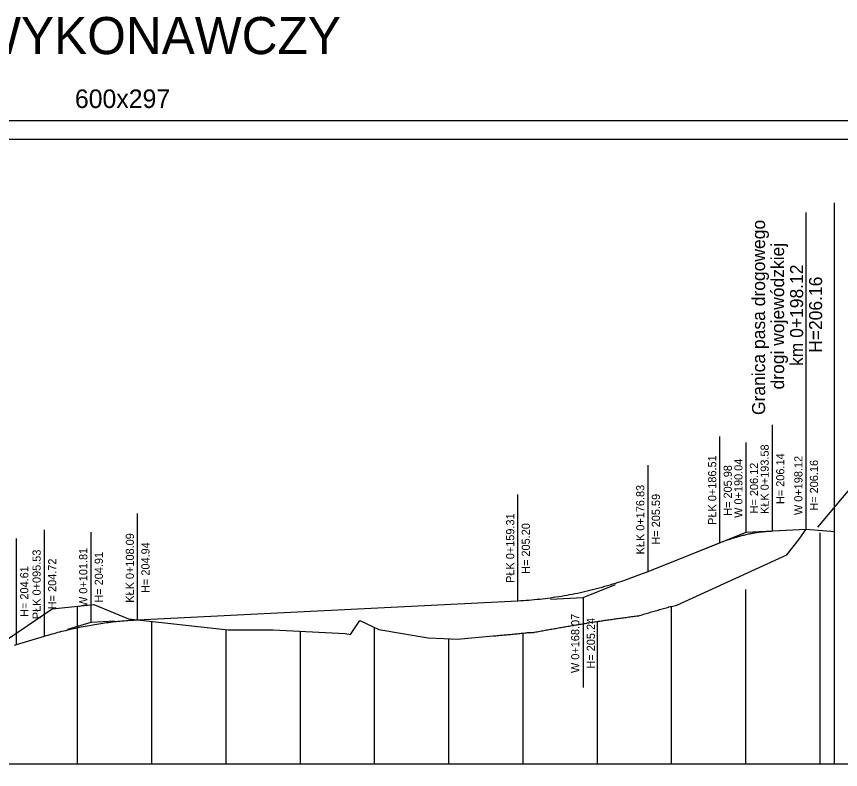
# Model space of a CAD drawing. Extents: x 6513080 to 6513380, y 6022307 to 6022469.
# Drawn here: x 6513209.5 to 6513320.4, y 6022367.8 to 6022469.3 of the extents above; entities that cross this region are included whole.
import ezdxf

# ---------------------------------------------------------------- set-up
doc = ezdxf.new("R2010")
doc.units = 0
for name, color, linetype in [('1', 7, 'Continuous'), ('42', 7, 'Continuous'), ('CONSTRUCTION_CLASS', 7, 'Continuous'), ('maxp_opisy', 7, 'Continuous'), ('maxp_ramka_2', 7, 'Continuous')]:
    doc.layers.add(name, color=color, linetype=linetype)

msp = doc.modelspace()

# ---------------------------------------------------------------- linework, layer by layer
for p, q in [((6513294.53, 6022394.49), (6513307.74, 6022399.78)), ((6513307.74, 6022399.78), (6513315.82, 6022400.17)), ((6513311.28, 6022399.95), (6513315.82, 6022400.17)), ((6513294.53, 6022394.49), (6513304.21, 6022398.37)), ((6513225.79, 6022387.98), (6513277.01, 6022390.55)), ((6513225.79, 6022387.98), (6513277.01, 6022390.55)), ((6513209.47, 6022384.65), (6513213.23, 6022385.78)), ((6513209.47, 6022384.65), (6513213.23, 6022385.78))]:
    msp.add_line(p, q)
for points in [[(6513304.21, 6022398.37), (6513304.36, 6022398.43), (6513304.51, 6022398.49), (6513304.65, 6022398.54), (6513304.8, 6022398.6), (6513304.95, 6022398.65), (6513305.1, 6022398.7), (6513305.24, 6022398.76), (6513305.39, 6022398.81), (6513305.54, 6022398.86), (6513305.68, 6022398.91), (6513305.83, 6022398.95), (6513305.98, 6022399), (6513306.13, 6022399.04), (6513306.27, 6022399.09), (6513306.42, 6022399.13), (6513306.57, 6022399.17), (6513306.71, 6022399.22), (6513306.86, 6022399.26), (6513307.01, 6022399.29), (6513307.16, 6022399.33), (6513307.3, 6022399.37), (6513307.45, 6022399.4), (6513307.6, 6022399.44), (6513307.89, 6022399.51), (6513308.04, 6022399.54), (6513308.19, 6022399.57), (6513308.33, 6022399.6), (6513308.48, 6022399.62), (6513308.63, 6022399.65), (6513308.78, 6022399.68), (6513308.92, 6022399.7), (6513309.07, 6022399.73), (6513309.22, 6022399.75), (6513309.36, 6022399.77), (6513309.51, 6022399.79), (6513309.66, 6022399.81), (6513309.81, 6022399.83), (6513309.95, 6022399.84), (6513310.1, 6022399.86), (6513310.25, 6022399.88), (6513310.39, 6022399.89), (6513310.54, 6022399.9), (6513310.69, 6022399.91), (6513310.84, 6022399.93), (6513310.98, 6022399.94), (6513311.13, 6022399.94), (6513311.28, 6022399.95)], [(6513277.01, 6022390.55), (6513277.38, 6022390.57), (6513277.74, 6022390.59), (6513278.11, 6022390.61), (6513278.47, 6022390.64), (6513278.84, 6022390.67), (6513279.2, 6022390.7), (6513279.57, 6022390.74), (6513279.93, 6022390.78), (6513280.3, 6022390.82), (6513280.66, 6022390.86), (6513281.03, 6022390.91), (6513281.39, 6022390.96), (6513281.76, 6022391.01), (6513282.12, 6022391.06), (6513282.49, 6022391.12), (6513282.85, 6022391.18), (6513283.22, 6022391.24), (6513283.58, 6022391.31), (6513283.95, 6022391.37), (6513284.31, 6022391.44), (6513284.68, 6022391.52), (6513285.04, 6022391.59), (6513285.41, 6022391.67), (6513286.14, 6022391.84), (6513286.5, 6022391.92), (6513286.87, 6022392.01), (6513287.23, 6022392.1), (6513287.6, 6022392.2), (6513287.96, 6022392.29), (6513288.33, 6022392.39), (6513288.69, 6022392.5), (6513289.06, 6022392.6), (6513289.42, 6022392.71), (6513289.79, 6022392.82), (6513290.15, 6022392.93), (6513290.52, 6022393.05), (6513290.88, 6022393.16), (6513291.25, 6022393.29), (6513291.61, 6022393.41), (6513291.98, 6022393.54), (6513292.34, 6022393.66), (6513292.71, 6022393.8), (6513293.07, 6022393.93), (6513293.44, 6022394.07), (6513293.8, 6022394.21), (6513294.17, 6022394.35), (6513294.53, 6022394.49)], [(6513277.01, 6022390.55), (6513277.38, 6022390.57), (6513277.74, 6022390.59), (6513278.11, 6022390.61), (6513278.47, 6022390.64), (6513278.84, 6022390.67), (6513279.2, 6022390.7), (6513279.57, 6022390.74), (6513279.93, 6022390.78), (6513280.3, 6022390.82), (6513280.66, 6022390.86), (6513281.03, 6022390.91), (6513281.39, 6022390.96), (6513281.76, 6022391.01), (6513282.12, 6022391.06), (6513282.49, 6022391.12), (6513282.85, 6022391.18), (6513283.22, 6022391.24), (6513283.58, 6022391.31), (6513283.95, 6022391.37), (6513284.31, 6022391.44), (6513284.68, 6022391.52), (6513285.04, 6022391.59), (6513285.41, 6022391.67), (6513286.14, 6022391.84), (6513286.5, 6022391.92), (6513286.87, 6022392.01), (6513287.23, 6022392.1), (6513287.6, 6022392.2), (6513287.96, 6022392.29), (6513288.33, 6022392.39), (6513288.69, 6022392.5), (6513289.06, 6022392.6), (6513289.42, 6022392.71), (6513289.79, 6022392.82), (6513290.15, 6022392.93), (6513290.52, 6022393.05), (6513290.88, 6022393.16), (6513291.25, 6022393.29), (6513291.61, 6022393.41), (6513291.98, 6022393.54), (6513292.34, 6022393.66), (6513292.71, 6022393.8), (6513293.07, 6022393.93), (6513293.44, 6022394.07), (6513293.8, 6022394.21), (6513294.17, 6022394.35), (6513294.53, 6022394.49)], [(6513213.23, 6022385.78), (6513213.49, 6022385.86), (6513213.75, 6022385.93), (6513214.01, 6022386.01), (6513214.27, 6022386.08), (6513214.54, 6022386.15), (6513214.8, 6022386.23), (6513215.06, 6022386.3), (6513215.32, 6022386.36), (6513215.58, 6022386.43), (6513215.84, 6022386.5), (6513216.11, 6022386.56), (6513216.37, 6022386.62), (6513216.63, 6022386.69), (6513216.89, 6022386.75), (6513217.15, 6022386.81), (6513217.41, 6022386.86), (6513217.68, 6022386.92), (6513217.94, 6022386.97), (6513218.2, 6022387.03), (6513218.46, 6022387.08), (6513218.72, 6022387.13), (6513218.98, 6022387.18), (6513219.25, 6022387.23), (6513219.77, 6022387.32), (6513220.03, 6022387.36), (6513220.29, 6022387.41), (6513220.55, 6022387.45), (6513220.82, 6022387.49), (6513221.08, 6022387.53), (6513221.34, 6022387.56), (6513221.6, 6022387.6), (6513221.86, 6022387.63), (6513222.12, 6022387.67), (6513222.39, 6022387.7), (6513222.65, 6022387.73), (6513222.91, 6022387.76), (6513223.17, 6022387.78), (6513223.43, 6022387.81), (6513223.69, 6022387.83), (6513223.96, 6022387.86), (6513224.22, 6022387.88), (6513224.48, 6022387.9), (6513224.74, 6022387.92), (6513225, 6022387.94), (6513225.26, 6022387.95), (6513225.53, 6022387.97), (6513225.79, 6022387.98)], [(6513213.23, 6022385.78), (6513213.49, 6022385.86), (6513213.75, 6022385.93), (6513214.01, 6022386.01), (6513214.27, 6022386.08), (6513214.54, 6022386.15), (6513214.8, 6022386.23), (6513215.06, 6022386.3), (6513215.32, 6022386.36), (6513215.58, 6022386.43), (6513215.84, 6022386.5), (6513216.11, 6022386.56), (6513216.37, 6022386.62), (6513216.63, 6022386.69), (6513216.89, 6022386.75), (6513217.15, 6022386.81), (6513217.41, 6022386.86), (6513217.68, 6022386.92), (6513217.94, 6022386.97), (6513218.2, 6022387.03), (6513218.46, 6022387.08), (6513218.72, 6022387.13), (6513218.98, 6022387.18), (6513219.25, 6022387.23), (6513219.77, 6022387.32), (6513220.03, 6022387.36), (6513220.29, 6022387.41), (6513220.55, 6022387.45), (6513220.82, 6022387.49), (6513221.08, 6022387.53), (6513221.34, 6022387.56), (6513221.6, 6022387.6), (6513221.86, 6022387.63), (6513222.12, 6022387.67), (6513222.39, 6022387.7), (6513222.65, 6022387.73), (6513222.91, 6022387.76), (6513223.17, 6022387.78), (6513223.43, 6022387.81), (6513223.69, 6022387.83), (6513223.96, 6022387.86), (6513224.22, 6022387.88), (6513224.48, 6022387.9), (6513224.74, 6022387.92), (6513225, 6022387.94), (6513225.26, 6022387.95), (6513225.53, 6022387.97), (6513225.79, 6022387.98)], [(6513209.21, 6022384.57), (6513209.47, 6022384.65)], [(6513209.21, 6022384.57), (6513209.47, 6022384.65)]]:
    msp.add_lwpolyline(points)
at = {"layer": '1'}
for p, q in [((6513305.98, 6022399.08), (6513307.74, 6022399.78)), ((6513307.74, 6022399.78), (6513309.51, 6022399.87)), ((6513315.82, 6022400.17), (6513319.69, 6022399.86)), ((6513317.7, 6022368.56), (6513317.7, 6022399.68)), ((6513285.77, 6022390.98), (6513290.15, 6022392.74)), ((6513307.7, 6022368.56), (6513307.7, 6022392.05)), ((6513281.39, 6022390.77), (6513285.77, 6022390.98)), ((6513217.7, 6022368.56), (6513217.7, 6022389.82)), ((6513297.7, 6022368.56), (6513297.7, 6022389.79)), ((6513216.37, 6022386.72), (6513219.51, 6022387.67)), ((6513219.51, 6022387.67), (6513222.65, 6022387.83)), ((6513227.7, 6022368.56), (6513227.7, 6022387.76)), ((6513287.7, 6022368.56), (6513287.7, 6022387.76)), ((6513237.7, 6022368.56), (6513237.7, 6022386.66)), ((6513247.7, 6022368.56), (6513247.7, 6022386.46)), ((6513257.7, 6022368.56), (6513257.7, 6022386.96)), ((6513277.7, 6022368.56), (6513277.7, 6022386.19)), ((6513267.7, 6022368.56), (6513267.7, 6022385.43)), ((6513217.7, 6022368.56), (6513217.7, 6022370.56)), ((6513227.7, 6022368.56), (6513227.7, 6022369.56)), ((6513237.7, 6022368.56), (6513237.7, 6022369.56)), ((6513247.7, 6022368.56), (6513247.7, 6022369.56)), ((6513257.7, 6022368.56), (6513257.7, 6022369.56)), ((6513267.7, 6022368.56), (6513267.7, 6022369.56)), ((6513277.7, 6022368.56), (6513277.7, 6022369.56)), ((6513287.7, 6022368.56), (6513287.7, 6022369.56)), ((6513297.7, 6022368.56), (6513297.7, 6022369.56)), ((6513307.7, 6022368.56), (6513307.7, 6022369.56)), ((6513317.7, 6022368.56), (6513317.7, 6022370.56)), ((6513117.7, 6022368.56), (6513327.7, 6022368.56))]:
    msp.add_line(p, q, dxfattribs=at)
msp.add_lwpolyline([(6513207.39, 6022384.79), (6513214.28, 6022389.47), (6513219.87, 6022390.04), (6513224.57, 6022388.1), (6513237.96, 6022386.63), (6513244.04, 6022386.65), (6513253.74, 6022386.15), (6513254.46, 6022386.02), (6513255.73, 6022387.88), (6513258.29, 6022386.69), (6513264.93, 6022385.53), (6513267.02, 6022385.47), (6513268.82, 6022385.37), (6513273.67, 6022385.81), (6513273.85, 6022385.82), (6513274.03, 6022385.84), (6513274.21, 6022385.85), (6513274.39, 6022385.87), (6513274.57, 6022385.89), (6513274.75, 6022385.9), (6513274.93, 6022385.92), (6513275.11, 6022385.94), (6513275.29, 6022385.95), (6513275.46, 6022385.97), (6513275.64, 6022385.99), (6513275.82, 6022386), (6513276, 6022386.02), (6513276.18, 6022386.04), (6513276.36, 6022386.06), (6513276.54, 6022386.07), (6513276.72, 6022386.09), (6513276.9, 6022386.11), (6513277.08, 6022386.13), (6513277.26, 6022386.14), (6513277.44, 6022386.16), (6513277.61, 6022386.18), (6513277.79, 6022386.2), (6513277.97, 6022386.22), (6513278.15, 6022386.23), (6513278.28, 6022386.25), (6513278.33, 6022386.25), (6513278.51, 6022386.26), (6513278.69, 6022386.27), (6513278.87, 6022386.28), (6513279.05, 6022386.29), (6513279.14, 6022386.29), (6513279.23, 6022386.31), (6513279.41, 6022386.34), (6513279.59, 6022386.38), (6513279.76, 6022386.41), (6513279.94, 6022386.44), (6513280.12, 6022386.48), (6513280.3, 6022386.51), (6513280.48, 6022386.54), (6513280.66, 6022386.58), (6513280.84, 6022386.61), (6513281.02, 6022386.64), (6513281.2, 6022386.67), (6513281.38, 6022386.71), (6513281.56, 6022386.74), (6513281.74, 6022386.77), (6513281.91, 6022386.8), (6513282.09, 6022386.83), (6513282.27, 6022386.87), (6513282.45, 6022386.9), (6513282.63, 6022386.93), (6513282.81, 6022386.96), (6513282.99, 6022386.99), (6513283.17, 6022387.02), (6513283.35, 6022387.05), (6513283.53, 6022387.08), (6513283.71, 6022387.11), (6513283.89, 6022387.14), (6513284.06, 6022387.17), (6513284.24, 6022387.2), (6513284.42, 6022387.23), (6513284.6, 6022387.26), (6513284.78, 6022387.29), (6513284.96, 6022387.32), (6513285.14, 6022387.35), (6513285.32, 6022387.38), (6513285.5, 6022387.41), (6513285.68, 6022387.44), (6513285.86, 6022387.47), (6513286.04, 6022387.5), (6513286.22, 6022387.53), (6513286.39, 6022387.55), (6513286.57, 6022387.58), (6513286.75, 6022387.61), (6513286.93, 6022387.64), (6513287.11, 6022387.67), (6513287.29, 6022387.69), (6513287.47, 6022387.72), (6513287.65, 6022387.75), (6513287.83, 6022387.78), (6513288.01, 6022387.8), (6513288.19, 6022387.83), (6513288.37, 6022387.86), (6513288.54, 6022387.88), (6513288.72, 6022387.91), (6513288.9, 6022387.94), (6513289.08, 6022387.96), (6513289.26, 6022387.99), (6513289.44, 6022388.01), (6513289.62, 6022388.04), (6513289.8, 6022388.07), (6513289.98, 6022388.09), (6513290.16, 6022388.12), (6513290.34, 6022388.14), (6513290.52, 6022388.17), (6513290.69, 6022388.19), (6513290.87, 6022388.22), (6513291.05, 6022388.24), (6513291.23, 6022388.26), (6513291.41, 6022388.29), (6513291.59, 6022388.31), (6513291.77, 6022388.34), (6513291.95, 6022388.36), (6513292.13, 6022388.38), (6513292.31, 6022388.41), (6513292.49, 6022388.43), (6513292.67, 6022388.45), (6513292.84, 6022388.47), (6513293.02, 6022388.5), (6513293.2, 6022388.52), (6513293.27, 6022388.53), (6513293.38, 6022388.56), (6513293.56, 6022388.62), (6513293.74, 6022388.67), (6513293.92, 6022388.72), (6513294.1, 6022388.78), (6513294.28, 6022388.83), (6513294.46, 6022388.88), (6513294.64, 6022388.94), (6513294.82, 6022388.99), (6513294.99, 6022389.04), (6513295.17, 6022389.09), (6513295.35, 6022389.15), (6513295.53, 6022389.2), (6513295.71, 6022389.25), (6513295.89, 6022389.3), (6513296.07, 6022389.35), (6513296.25, 6022389.41), (6513296.43, 6022389.46), (6513296.61, 6022389.51), (6513296.79, 6022389.56), (6513296.97, 6022389.61), (6513297.14, 6022389.66), (6513297.3, 6022389.7), (6513297.32, 6022389.71), (6513297.5, 6022389.75), (6513297.68, 6022389.78), (6513297.86, 6022389.82), (6513298.04, 6022389.86), (6513298.22, 6022389.9), (6513298.4, 6022389.94), (6513313.2, 6022396.72), (6513314.86, 6022398.86), (6513315.82, 6022400.17)], dxfattribs=at)
at = {"layer": '42'}
for p, q in [((6513319.62, 6022368.56), (6513319.62, 6022444.15)), ((6513315.82, 6022400.17), (6513315.82, 6022442.86)), ((6513311.28, 6022399.95), (6513311.28, 6022414.25)), ((6513304.21, 6022398.37), (6513304.21, 6022412.67)), ((6513307.74, 6022399.78), (6513307.74, 6022411.88)), ((6513315.82, 6022400.17), (6513315.82, 6022412.27)), ((6513294.53, 6022394.49), (6513294.53, 6022408.79)), ((6513323.46, 6022407.75), (6513317.33, 6022400.48)), ((6513277.01, 6022390.55), (6513277.01, 6022404.85)), ((6513225.79, 6022387.98), (6513225.79, 6022402.28)), ((6513213.23, 6022385.78), (6513213.23, 6022400.08)), ((6513219.51, 6022387.67), (6513219.51, 6022399.77)), ((6513311.28, 6022399.95), (6513315.82, 6022400.17)), ((6513209.47, 6022384.65), (6513209.47, 6022398.95)), ((6513294.53, 6022394.49), (6513304.21, 6022398.37)), ((6513285.77, 6022390.98), (6513285.77, 6022378.88)), ((6513225.79, 6022387.98), (6513277.01, 6022390.55)), ((6513209.47, 6022384.65), (6513213.23, 6022385.78))]:
    msp.add_line(p, q, dxfattribs=at)
for points in [[(6513304.21, 6022398.37), (6513304.36, 6022398.43), (6513304.51, 6022398.49), (6513304.65, 6022398.54), (6513304.8, 6022398.6), (6513304.95, 6022398.65), (6513305.1, 6022398.7), (6513305.24, 6022398.76), (6513305.39, 6022398.81), (6513305.54, 6022398.86), (6513305.68, 6022398.91), (6513305.83, 6022398.95), (6513305.98, 6022399), (6513306.13, 6022399.04), (6513306.27, 6022399.09), (6513306.42, 6022399.13), (6513306.57, 6022399.17), (6513306.71, 6022399.22), (6513306.86, 6022399.26), (6513307.01, 6022399.29), (6513307.16, 6022399.33), (6513307.3, 6022399.37), (6513307.45, 6022399.4), (6513307.6, 6022399.44), (6513307.89, 6022399.51), (6513308.04, 6022399.54), (6513308.19, 6022399.57), (6513308.33, 6022399.6), (6513308.48, 6022399.62), (6513308.63, 6022399.65), (6513308.78, 6022399.68), (6513308.92, 6022399.7), (6513309.07, 6022399.73), (6513309.22, 6022399.75), (6513309.36, 6022399.77), (6513309.51, 6022399.79), (6513309.66, 6022399.81), (6513309.81, 6022399.83), (6513309.95, 6022399.84), (6513310.1, 6022399.86), (6513310.25, 6022399.88), (6513310.39, 6022399.89), (6513310.54, 6022399.9), (6513310.69, 6022399.91), (6513310.84, 6022399.93), (6513310.98, 6022399.94), (6513311.13, 6022399.94), (6513311.28, 6022399.95)], [(6513277.01, 6022390.55), (6513277.38, 6022390.57), (6513277.74, 6022390.59), (6513278.11, 6022390.61), (6513278.47, 6022390.64), (6513278.84, 6022390.67), (6513279.2, 6022390.7), (6513279.57, 6022390.74), (6513279.93, 6022390.78), (6513280.3, 6022390.82), (6513280.66, 6022390.86), (6513281.03, 6022390.91), (6513281.39, 6022390.96), (6513281.76, 6022391.01), (6513282.12, 6022391.06), (6513282.49, 6022391.12), (6513282.85, 6022391.18), (6513283.22, 6022391.24), (6513283.58, 6022391.31), (6513283.95, 6022391.37), (6513284.31, 6022391.44), (6513284.68, 6022391.52), (6513285.04, 6022391.59), (6513285.41, 6022391.67), (6513286.14, 6022391.84), (6513286.5, 6022391.92), (6513286.87, 6022392.01), (6513287.23, 6022392.1), (6513287.6, 6022392.2), (6513287.96, 6022392.29), (6513288.33, 6022392.39), (6513288.69, 6022392.5), (6513289.06, 6022392.6), (6513289.42, 6022392.71), (6513289.79, 6022392.82), (6513290.15, 6022392.93), (6513290.52, 6022393.05), (6513290.88, 6022393.16), (6513291.25, 6022393.29), (6513291.61, 6022393.41), (6513291.98, 6022393.54), (6513292.34, 6022393.66), (6513292.71, 6022393.8), (6513293.07, 6022393.93), (6513293.44, 6022394.07), (6513293.8, 6022394.21), (6513294.17, 6022394.35), (6513294.53, 6022394.49)], [(6513213.23, 6022385.78), (6513213.49, 6022385.86), (6513213.75, 6022385.93), (6513214.01, 6022386.01), (6513214.27, 6022386.08), (6513214.54, 6022386.15), (6513214.8, 6022386.23), (6513215.06, 6022386.3), (6513215.32, 6022386.36), (6513215.58, 6022386.43), (6513215.84, 6022386.5), (6513216.11, 6022386.56), (6513216.37, 6022386.62), (6513216.63, 6022386.69), (6513216.89, 6022386.75), (6513217.15, 6022386.81), (6513217.41, 6022386.86), (6513217.68, 6022386.92), (6513217.94, 6022386.97), (6513218.2, 6022387.03), (6513218.46, 6022387.08), (6513218.72, 6022387.13), (6513218.98, 6022387.18), (6513219.25, 6022387.23), (6513219.77, 6022387.32), (6513220.03, 6022387.36), (6513220.29, 6022387.41), (6513220.55, 6022387.45), (6513220.82, 6022387.49), (6513221.08, 6022387.53), (6513221.34, 6022387.56), (6513221.6, 6022387.6), (6513221.86, 6022387.63), (6513222.12, 6022387.67), (6513222.39, 6022387.7), (6513222.65, 6022387.73), (6513222.91, 6022387.76), (6513223.17, 6022387.78), (6513223.43, 6022387.81), (6513223.69, 6022387.83), (6513223.96, 6022387.86), (6513224.22, 6022387.88), (6513224.48, 6022387.9), (6513224.74, 6022387.92), (6513225, 6022387.94), (6513225.26, 6022387.95), (6513225.53, 6022387.97), (6513225.79, 6022387.98)], [(6513209.21, 6022384.57), (6513209.47, 6022384.65)]]:
    msp.add_lwpolyline(points, dxfattribs=at)
at = {"layer": 'maxp_ramka_2'}
for points in [[(6513079.9, 6022455.24), (6513379.9, 6022455.24), (6513379.9, 6022306.74), (6513079.9, 6022306.74)], [(6513092.4, 6022309.24), (6513092.4, 6022452.74), (6513377.4, 6022452.74), (6513377.4, 6022309.24)]]:
    msp.add_lwpolyline(points, close=True, dxfattribs=at)

# ---------------------------------------------------------------- texts
at = {"layer": '42'}
for s, p in [('KŁK 0+193.58', (6513310.78, 6022402.24)), ('PŁK 0+186.51', (6513303.71, 6022400.77)), ('W 0+190.04', (6513307.24, 6022401.71)), ('H= 206.14', (6513312.88, 6022403.57)), ('W 0+198.12', (6513315.32, 6022402.09)), ('H= 206.16', (6513317.42, 6022402.68)), ('H= 205.98', (6513305.81, 6022401.99)), ('H= 206.12', (6513309.34, 6022402.31)), ('KŁK 0+176.83', (6513294.03, 6022396.79)), ('H= 205.59', (6513296.13, 6022398.11)), ('PŁK 0+159.31', (6513276.51, 6022392.95)), ('H= 205.20', (6513278.61, 6022394.17)), ('KŁK 0+108.09', (6513225.29, 6022390.28)), ('H= 204.94', (6513227.39, 6022391.6)), ('PŁK 0+095.53', (6513212.73, 6022388.07)), ('W 0+101.81', (6513219.01, 6022389.7)), ('H= 204.72', (6513214.83, 6022389.4)), ('H= 204.91', (6513221.11, 6022390.29)), ('H= 204.61', (6513211.07, 6022388.37)), ('W 0+168.07', (6513285.27, 6022380.81)), ('H= 205.24', (6513287.37, 6022381.41))]:
    msp.add_text(s, height=1.1, rotation=90, dxfattribs=at).set_placement(p)
at = {"layer": 'CONSTRUCTION_CLASS'}
for s, height, p in [('WYKONAWCZY', 5, (6513203.77, 6022464.18)), ('600x297', 2.5, (6513217.34, 6022456.92))]:
    msp.add_text(s, height=height, rotation=0.0002, dxfattribs=at).set_placement(p)
at = {"layer": 'maxp_opisy'}
for s, p in [('Granica pasa drogowego ', (6513310.29, 6022415.56)), ('drogi wojewódzkiej', (6513312.85, 6022419.01)), ('km 0+198.12', (6513315.41, 6022422.17)), ('H=206.16', (6513317.97, 6022423.94))]:
    msp.add_text(s, height=1.76, rotation=90.0162, dxfattribs=at).set_placement(p)

doc.saveas('drawing.dxf')
